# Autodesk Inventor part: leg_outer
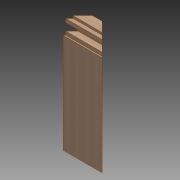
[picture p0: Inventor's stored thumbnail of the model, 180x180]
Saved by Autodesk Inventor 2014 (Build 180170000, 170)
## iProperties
Created: 2014-05
Part Number: leg_outer
Material: Maple
Document SubType Name: Modeling
Designer: t_emanb
Density: 1 g/cm^3
Appearance: Maple - Solid Natural Medium Gloss
Author: t_emanb
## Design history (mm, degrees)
sketch "Sketch1"
  geometry: L1 (0, 0)-(101.6, 0); L2 (101.6, 0)-(101.6, 38.1); L3 (101.6, 38.1)-(0, 38.1); L4 (0, 38.1)-(0, 0)
  constraints: 8 end point, 2 parallel, 1 horizontal, 1 perpendicular
  dimensions: "d0" = 101.6 distance of L2.end L3.end; "d1" = 38.1 distance of L3.end L1.start
extrude "Extrusion1" new body sketch "Sketch1" distance "d2" = 304.8; taper "d3" = 0 deg
sketch "Sketch2"
  geometry: L1 (0, 304.8)-(38.1, 304.8) reference; L2 (0, 0)-(0, 304.8) reference; L3 (0, 288.925)-(19.05, 288.925); L4 (19.05, 288.925)-(19.05, 269.875); L5 (19.05, 269.875)-(0, 269.875)
  constraints: 6 end point, 3 perpendicular, 2 point on line
  dimensions: "d4" = 19.05 distance of L3.end L4.end; "d5" = 19.05 distance between parallel lines of L2 L4; "d6" = 15.875 distance between parallel lines of L1 L3
extrude "Extrusion2" cut sketch "Sketch2" stored distance "d7" = 266.7; taper "d8" = 0 deg
sketch "Sketch7"
  geometry: L1 (0, 304.8)-(38.1, 304.8) reference; L2 (0, 288.925)-(0, 304.8) reference; L3 (12.7, 298.45)-(12.7, 304.8); L4 (0, 298.45)-(12.7, 298.45)
  constraints: 4 end point, 2 perpendicular, 2 point on line
  dimensions: "d25" = 12.7 distance between parallel lines of L2 L3; "d26" = 6.35 distance between parallel lines of L1 L4
extrude "Extrusion7" cut sketch "Sketch7" stored distance "d27" = 266.7; taper "d28" = 0 deg
sketch "Sketch3"
  geometry: L1 (0, 288.925)-(19.05, 288.925) reference; L2 (19.05, 269.875)-(0, 269.875) reference; L3 (0, 0)-(0, 269.875) reference; L4 (0, 304.8)-(38.1, 304.8) reference; L5 (0, 288.925)-(0, 304.8) reference; L6 (3.099, 260.35)-(0, 260.35); L7 (3.099, 304.8)-(3.099, 288.925); L8 (3.099, 269.875)-(3.099, 260.35); L9 (12.7, 298.45)-(0, 298.45) reference
  constraints: 6 end point, 4 point on line, 2 parallel, 1 collinear, 1 perpendicular
  dimensions: "d9" = 3.0988 distance of L6.start L6.end; "d29" = 38.1 distance between parallel lines of L6 L9
extrude "Extrusion3" cut sketch "Sketch3" stored distance "d11" = 266.7; taper "d12" = 0 deg
sketch "Sketch5"
  geometry: L1 (0, 0)-(-101.6, 0) reference; L2 (0, 38.1)-(0, 0) reference; L3 (-101.6, 0)-(-101.6, 38.1) reference; L4 (-101.6, 38.1)-(-63.5, 0); L5 (0, 38.1)-(-38.1, 0)
  constraints: 4 end point, 2 point on line
  dimensions: "d17" = 135 deg angle of L3 L4; "d18" = 45 deg angle of L2 L5
extrude "Extrusion5" cut sketch "Sketch5" stored distance "d19" = 266.7; taper "d20" = 0 deg
sketch "Sketch6"
  geometry: L1 (0, 19.05)-(0, 0) reference; L2 (63.5, 0)-(63.5, 19.05) reference; L3 (63.5, 9.525)-(0, 9.525); C1 r 6.35 at (31.75, 9.525); 1 further point
  constraints: 3 midpoint, 2 end point, 1 centre point
  dimensions: "d21" = 12.7 diameter of C1
extrude "Extrusion6" cut sketch "Sketch6" stored distance "d22" = 266.7; taper "d23" = 0 deg
body "Solid1"
